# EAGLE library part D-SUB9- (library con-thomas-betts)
D-Subminiatur Connector Source: Electronioc Interconnects European Edition 1998
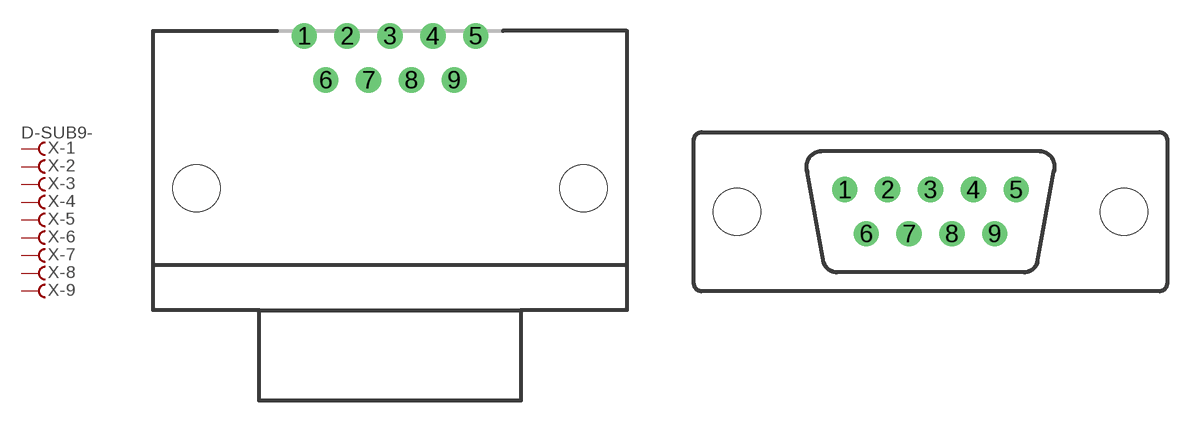
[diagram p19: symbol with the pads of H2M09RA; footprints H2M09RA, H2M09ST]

Designator prefix X; gates -1=FV -2=F -3=F -4=F -5=F -6=F -7=F -8=F -9=F

## D-SUB9-H2M09RA (OC_FARNELL: unknown; OC_NEWARK: unknown)  [H2M09RA]
1  -1:F  pas
2  -2:F  pas
3  -3:F  pas
4  -4:F  pas
5  -5:F  pas
6  -6:F  pas
7  -7:F  pas
8  -8:F  pas
9  -9:F  pas

## D-SUB9-H2M09ST (OC_FARNELL: unknown; OC_NEWARK: unknown)  [H2M09ST]
Pads as for H2M09RA

## D-SUB9-H2R09RA (OC_FARNELL: unknown; OC_NEWARK: unknown)  [H2R09RA]
Pads as for H2M09RA

## D-SUB9-H2R09ST (OC_FARNELL: unknown; OC_NEWARK: unknown)  [H2R09ST]
Pads as for H2M09RA

## D-SUB9-H3M09RA (OC_FARNELL: unknown; OC_NEWARK: unknown)  [H3M09RA]
Pads as for H2M09RA

## D-SUB9-H5M09RA (OC_FARNELL: unknown; OC_NEWARK: unknown)  [H5M09RA]
Pads as for H2M09RA

## Footprint H2M09RA (pad centres in mm)
THOMAS&BETTS H2M09RA29A
drill 1.092 round: 1 -5.537,7.925; 2 -2.769,7.925; 3 0,7.925; 4 2.769,7.925; 5 5.537,7.925; 6 -4.153,5.08; 7 -1.384,5.08; 8 1.384,5.08; 9 4.153,5.08
hole 3.048 at -12.497,-1.905
hole 3.048 at 12.497,-1.905

## Footprint H2M09ST (pad centres in mm)
THOMAS&BETTS H2M09ST29x
drill 1.092 round: 1 -5.537,1.422; 2 -2.769,1.422; 3 0,1.422; 4 2.769,1.422; 5 5.537,1.422; 6 -4.153,-1.422; 7 -1.384,-1.422; 8 1.384,-1.422; 9 4.153,-1.422
hole 3.048 at -12.497,0
hole 3.048 at 12.497,0

## Footprint H2R09RA (pad centres in mm)
THOMAS&BETTS H2R09RA29A
drill 1.092 round: 1 5.537,7.925; 2 2.769,7.925; 3 0,7.925; 4 -2.769,7.925; 5 -5.537,7.925; 6 4.153,5.08; 7 1.384,5.08; 8 -1.384,5.08; 9 -4.153,5.08
hole 3.048 at -12.497,-1.905
hole 3.048 at 12.497,-1.905

## Footprint H2R09ST (pad centres in mm)
THOMAS&BETTS H2R09ST29x
drill 1.092 round: 1 5.537,1.422; 2 2.769,1.422; 3 0,1.422; 4 -2.769,1.422; 5 -5.537,1.422; 6 4.153,-1.422; 7 1.384,-1.422; 8 -1.384,-1.422; 9 -4.153,-1.422
hole 3.048 at -12.497,0
hole 3.048 at 12.497,0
